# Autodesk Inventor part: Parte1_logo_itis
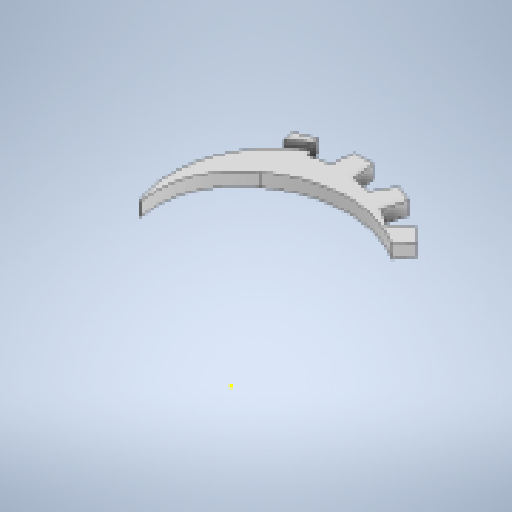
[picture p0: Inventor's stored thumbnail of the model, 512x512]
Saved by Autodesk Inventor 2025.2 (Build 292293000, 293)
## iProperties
Created: 2025-03
Part Number: Parte1_logo_itis
Material: Generico
Document SubType Name: Modeling
Designer: 18907419
Density: 1 g/cm^3
Appearance: Default
Author: 18907419
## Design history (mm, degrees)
sketch "Schizzo1"
  geometry: L1 (0, 0)-(198.619, 0); L2 (198.619, 0)-(198.619, -200); L3 (198.619, -200)-(0, -200); L4 (0, -200)-(0, 0); 1 other entity
  constraints: 2 other
  dimensions: "d1" = 200 distance of L3.end L1.start
  node "Immagine1"
sketch "Schizzo2"
  geometry: L1 (105.821, -199.217)-(91.821, -199.217); L2 (91.821, -199.217)-(89.861, -182.291); L3 (98.821, -199.217)-(98.821, -182.907); L4 (105.821, -199.217)-(107.782, -182.291); L5 (143.188, -189.466)-(130.253, -194.824); L6 (130.253, -194.824)-(121.965, -179.936); L7 (136.721, -192.145)-(130.479, -177.077); L8 (143.188, -189.466)-(138.521, -173.078); L9 (173.978, -166.158)-(164.079, -176.058); L10 (164.079, -176.058)-(150.724, -165.475); L11 (169.028, -171.108)-(157.495, -159.575); L12 (173.978, -166.158)-(163.395, -152.804); L13 (193.505, -132.842)-(188.148, -145.776); L14 (188.148, -145.776)-(171.76, -141.109); L15 (190.826, -139.309)-(175.758, -133.067); L16 (193.505, -132.842)-(178.617, -124.553); L17 (198.796, -94.588)-(198.796, -108.588); L18 (198.796, -108.588)-(181.87, -110.548); L19 (198.796, -101.588)-(182.486, -101.588); L20 (198.796, -94.588)-(181.87, -92.628); L21 (189.045, -57.222)-(194.403, -70.156); L22 (194.403, -70.156)-(179.515, -78.445); L23 (191.724, -63.689)-(176.655, -69.931); L24 (189.045, -57.222)-(172.657, -61.888); L25 (165.737, -26.431)-(175.637, -36.331); L26 (175.637, -36.331)-(165.054, -49.686); L27 (170.687, -31.381)-(159.154, -42.914); L28 (165.737, -26.431)-(152.382, -37.014); L29 (132.42, -6.904)-(145.355, -12.262); L30 (145.355, -12.262)-(140.688, -28.65); L31 (138.888, -9.583)-(132.646, -24.652); L32 (132.42, -6.904)-(124.132, -21.792); L33 (94.167, -1.614)-(108.167, -1.614); L34 (108.167, -1.614)-(110.127, -18.54); L35 (101.167, -1.614)-(101.167, -17.924); L36 (94.167, -1.614)-(92.207, -18.54); L37 (56.801, -11.364)-(69.735, -6.007); L38 (69.735, -6.007)-(78.023, -20.895); L39 (63.268, -8.686)-(69.51, -23.754); L40 (56.801, -11.364)-(61.467, -27.753); L41 (26.01, -34.672)-(35.91, -24.773); L42 (35.91, -24.773)-(49.265, -35.356); L43 (30.96, -29.723)-(42.493, -41.256); L44 (26.01, -34.672)-(36.593, -48.027); L45 (6.483, -67.989)-(11.841, -55.055); L46 (11.841, -55.055)-(28.229, -59.721); L47 (9.162, -61.522)-(24.231, -67.764); L48 (6.483, -67.989)-(21.371, -76.278); L49 (1.192, -106.243)-(1.192, -92.243); L50 (1.192, -92.243)-(18.119, -90.283); L51 (1.192, -99.243)-(17.503, -99.243); L52 (1.192, -106.243)-(18.119, -108.203); L53 (10.943, -143.609)-(5.586, -130.675); L54 (5.586, -130.675)-(20.474, -122.386); L55 (8.264, -137.142)-(23.333, -130.9); L56 (10.943, -143.609)-(27.331, -138.942); L57 (34.251, -174.399)-(24.352, -164.5); L58 (24.352, -164.5)-(34.935, -151.145); L59 (29.301, -169.45)-(40.835, -157.917); L60 (34.251, -174.399)-(47.606, -163.816); L61 (67.568, -193.926)-(54.634, -188.569); L62 (54.634, -188.569)-(59.3, -172.181); L63 (61.101, -191.248)-(67.343, -176.179); L64 (67.568, -193.926)-(75.856, -179.038); A1 r 82.5 centre (99.994, -100.415) between (89.861, -182.291) and (98.821, -182.907); A2 r 80 centre (81.89, -116.945) between (124.568, -184.611) and (153.002, -80.297); A3 r 85 centre (79.253, -82.612) between (32.823, -153.81) and (129.534, -151.145); A4 r 61.843 centre (94.454, -100.214) between (129.534, -151.145) and (153.002, -80.297); A5 r 55 centre (101.821, -141.774) between (127.729, -190.29) and (140.688, -180.688); 9 further points
  constraints: 128 end point, 11 point on circle, 5 centre point, 4 point on line, 1 horizontal, 1 midpoint, 1 symmetric about line, 1 vertical, 161 other
  dimensions: "d2" = 165 diameter of A1; "d3" = 14 distance of L1.start L1.end; "d6" = 360 deg dimension on A1.centre L1.start (derived); "d8" = 80 radius of A2; "d14" = 55 radius of A5
extrude "Estrusione1" new body sketch "Schizzo2" distance "d10" = 10; taper "d11" = 0 deg
fillet "Raccordo1" dims "d13" = 0.6
sketch "Schizzo3"
  geometry: 1 further point
node "Solido1"
node "Schizzo - Serie circolare1" dims "d6" = 360 deg (derived)
